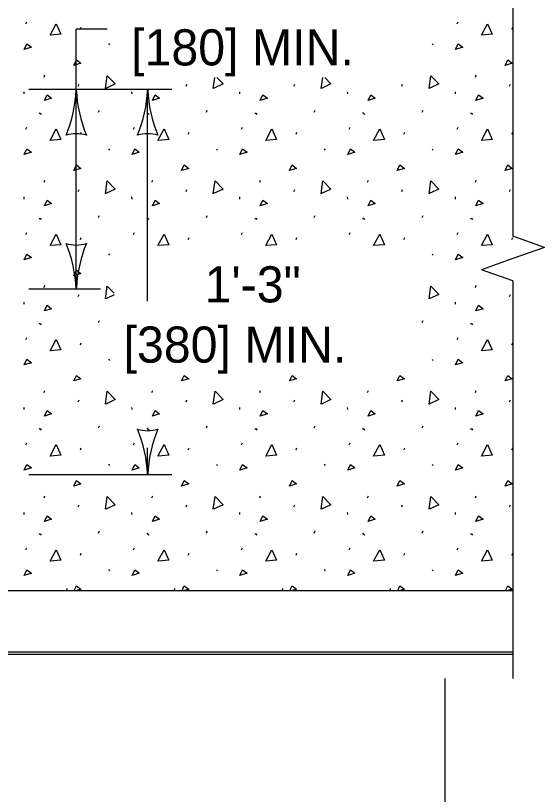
# Model space of a CAD drawing. Extents: x 49991.4 to 50021, y 49987.6 to 50011.4.
# Drawn here: x 50011.209 to 50012.088, y 49995.271 to 49996.564 of the extents above; entities that cross this region are included whole.
import ezdxf

# ---------------------------------------------------------------- set-up
doc = ezdxf.new("R2010")
doc.units = 0
for name, color, linetype in [('Level 1', 7, 'Continuous'), ('Level 2', 7, 'Continuous'), ('Level 3', 7, 'Continuous'), ('Level 6', 7, 'Continuous')]:
    doc.layers.add(name, color=color, linetype=linetype)

msp = doc.modelspace()

# ---------------------------------------------------------------- linework, layer by layer
at = {"layer": 'Level 1'}
for p, q in [((50011.2259, 49996.5503), (50011.2274, 49996.5536)), ((50011.3167, 49996.5417), (50011.3182, 49996.545)), ((50011.9425, 49996.5503), (50011.944, 49996.5536)), ((50012.0333, 49996.5417), (50012.0348, 49996.545)), ((50011.2233, 49996.5081), (50011.2278, 49996.5174)), ((50011.2352, 49996.5118), (50011.2233, 49996.5081)), ((50011.2278, 49996.5174), (50011.2352, 49996.5118)), ((50011.3633, 49996.5178), (50011.3648, 49996.5156)), ((50011.9008, 49996.5178), (50011.9023, 49996.5156)), ((50011.9399, 49996.5081), (50011.9444, 49996.5174)), ((50011.9519, 49996.5118), (50011.9399, 49996.5081)), ((50011.9444, 49996.5174), (50011.9519, 49996.5118)), ((50011.2563, 49996.4622), (50011.2577, 49996.4656)), ((50011.5375, 49996.4431), (50011.54, 49996.4614)), ((50011.7166, 49996.4431), (50011.7192, 49996.4614)), ((50011.9729, 49996.4622), (50011.9744, 49996.4656)), ((50011.3129, 49996.4469), (50011.3144, 49996.4503)), ((50011.4921, 49996.4469), (50011.4936, 49996.4503)), ((50011.6713, 49996.4469), (50011.6728, 49996.4503)), ((50011.8504, 49996.4469), (50011.8519, 49996.4503)), ((50012.0296, 49996.4469), (50012.0311, 49996.4503)), ((50011.2225, 49996.4376), (50011.2228, 49996.4342)), ((50011.4016, 49996.4376), (50011.402, 49996.4342)), ((50011.5808, 49996.4376), (50011.5812, 49996.4342)), ((50011.7599, 49996.4376), (50011.7603, 49996.4342)), ((50011.9391, 49996.4376), (50011.9395, 49996.4342)), ((50011.2479, 49996.4032), (50011.2494, 49996.4009)), ((50011.3469, 49996.4037), (50011.3484, 49996.407)), ((50011.4271, 49996.4032), (50011.4286, 49996.4009)), ((50011.526, 49996.4037), (50011.5275, 49996.407)), ((50011.6062, 49996.4032), (50011.6077, 49996.4009)), ((50011.7052, 49996.4037), (50011.7067, 49996.407)), ((50011.7854, 49996.4032), (50011.7869, 49996.4009)), ((50011.8844, 49996.4037), (50011.8859, 49996.407)), ((50011.9646, 49996.4032), (50011.966, 49996.4009)), ((50011.2499, 49996.4023), (50011.2514, 49996.4001)), ((50011.4291, 49996.4023), (50011.4306, 49996.4001)), ((50011.6082, 49996.4023), (50011.6097, 49996.4001)), ((50011.7874, 49996.4023), (50011.7889, 49996.4001)), ((50011.9665, 49996.4023), (50011.968, 49996.4001)), ((50011.2259, 49996.3755), (50011.2274, 49996.3789)), ((50011.4051, 49996.3755), (50011.4066, 49996.3789)), ((50011.5842, 49996.3755), (50011.5857, 49996.3789)), ((50011.7634, 49996.3755), (50011.7649, 49996.3789)), ((50011.9425, 49996.3755), (50011.944, 49996.3789)), ((50011.3167, 49996.367), (50011.3182, 49996.3703)), ((50011.4958, 49996.367), (50011.4973, 49996.3703)), ((50011.675, 49996.367), (50011.6765, 49996.3703)), ((50011.8541, 49996.367), (50011.8556, 49996.3703)), ((50012.0333, 49996.367), (50012.0348, 49996.3703)), ((50011.2233, 49996.3334), (50011.2278, 49996.3427)), ((50011.2278, 49996.3427), (50011.2352, 49996.3371)), ((50011.3633, 49996.3431), (50011.3648, 49996.3409)), ((50011.4025, 49996.3334), (50011.4069, 49996.3427)), ((50011.4069, 49996.3427), (50011.4144, 49996.3371)), ((50011.5425, 49996.3431), (50011.5439, 49996.3409)), ((50011.5816, 49996.3334), (50011.5861, 49996.3427)), ((50011.5861, 49996.3427), (50011.5936, 49996.3371)), ((50011.7216, 49996.3431), (50011.7231, 49996.3409)), ((50011.7608, 49996.3334), (50011.7653, 49996.3427)), ((50011.7653, 49996.3427), (50011.7727, 49996.3371)), ((50011.9008, 49996.3431), (50011.9023, 49996.3409)), ((50011.9399, 49996.3334), (50011.9444, 49996.3427)), ((50011.9444, 49996.3427), (50011.9519, 49996.3371)), ((50011.2352, 49996.3371), (50011.2233, 49996.3334)), ((50011.4144, 49996.3371), (50011.4025, 49996.3334)), ((50011.5936, 49996.3371), (50011.5816, 49996.3334)), ((50011.7727, 49996.3371), (50011.7608, 49996.3334)), ((50011.9519, 49996.3371), (50011.9399, 49996.3334)), ((50011.2563, 49996.2875), (50011.2577, 49996.2909)), ((50011.4354, 49996.2875), (50011.4369, 49996.2909)), ((50011.6146, 49996.2875), (50011.6161, 49996.2909)), ((50011.7937, 49996.2875), (50011.7952, 49996.2909)), ((50011.9729, 49996.2875), (50011.9744, 49996.2909)), ((50011.3129, 49996.2722), (50011.3144, 49996.2756)), ((50011.4921, 49996.2722), (50011.4936, 49996.2756)), ((50011.6713, 49996.2722), (50011.6728, 49996.2756)), ((50011.8504, 49996.2722), (50011.8519, 49996.2756)), ((50012.0296, 49996.2722), (50012.0311, 49996.2756)), ((50011.2225, 49996.2629), (50011.2228, 49996.2595)), ((50011.4016, 49996.2629), (50011.402, 49996.2595)), ((50011.5808, 49996.2629), (50011.5812, 49996.2595)), ((50011.7599, 49996.2629), (50011.7603, 49996.2595)), ((50011.9391, 49996.2629), (50011.9395, 49996.2595)), ((50011.2479, 49996.2285), (50011.2494, 49996.2262)), ((50011.2499, 49996.2276), (50011.2514, 49996.2254)), ((50011.3469, 49996.229), (50011.3484, 49996.2323)), ((50011.4271, 49996.2285), (50011.4286, 49996.2262)), ((50011.4291, 49996.2276), (50011.4306, 49996.2254)), ((50011.526, 49996.229), (50011.5275, 49996.2323)), ((50011.6062, 49996.2285), (50011.6077, 49996.2262)), ((50011.6082, 49996.2276), (50011.6097, 49996.2254)), ((50011.7052, 49996.229), (50011.7067, 49996.2323)), ((50011.7854, 49996.2285), (50011.7869, 49996.2262)), ((50011.7874, 49996.2276), (50011.7889, 49996.2254)), ((50011.8844, 49996.229), (50011.8859, 49996.2323)), ((50011.9646, 49996.2285), (50011.966, 49996.2262)), ((50011.9665, 49996.2276), (50011.968, 49996.2254)), ((50011.2259, 49996.2008), (50011.2274, 49996.2042)), ((50011.3167, 49996.1922), (50011.3182, 49996.1956)), ((50011.4051, 49996.2008), (50011.4066, 49996.2042)), ((50011.4958, 49996.1922), (50011.4973, 49996.1956)), ((50011.5842, 49996.2008), (50011.5857, 49996.2042)), ((50011.675, 49996.1922), (50011.6765, 49996.1956)), ((50011.7634, 49996.2008), (50011.7649, 49996.2042)), ((50011.8541, 49996.1922), (50011.8556, 49996.1956)), ((50011.9425, 49996.2008), (50011.944, 49996.2042)), ((50012.0333, 49996.1922), (50012.0348, 49996.1956)), ((50011.2233, 49996.1587), (50011.2278, 49996.168)), ((50011.2352, 49996.1624), (50011.2233, 49996.1587)), ((50011.2278, 49996.168), (50011.2352, 49996.1624)), ((50011.3633, 49996.1684), (50011.3648, 49996.1661)), ((50011.9008, 49996.1684), (50011.9023, 49996.1661)), ((50011.9399, 49996.1587), (50011.9444, 49996.168)), ((50011.9519, 49996.1624), (50011.9399, 49996.1587)), ((50011.9444, 49996.168), (50011.9519, 49996.1624)), ((50011.2563, 49996.1128), (50011.2577, 49996.1162)), ((50011.9729, 49996.1128), (50011.9744, 49996.1162)), ((50011.3129, 49996.0975), (50011.3144, 49996.1009)), ((50011.3725, 49996.1002), (50011.3587, 49996.0938)), ((50012.0296, 49996.0975), (50012.0311, 49996.1009)), ((50011.2225, 49996.0881), (50011.2228, 49996.0848)), ((50011.9391, 49996.0881), (50011.9395, 49996.0848)), ((50011.2479, 49996.0537), (50011.2494, 49996.0515)), ((50011.3469, 49996.0542), (50011.3484, 49996.0576)), ((50011.8844, 49996.0542), (50011.8859, 49996.0576)), ((50011.9646, 49996.0537), (50011.966, 49996.0515)), ((50011.2499, 49996.0529), (50011.2514, 49996.0507)), ((50011.9665, 49996.0529), (50011.968, 49996.0507)), ((50011.2259, 49996.0261), (50011.2274, 49996.0295)), ((50011.9425, 49996.0261), (50011.944, 49996.0295)), ((50011.3167, 49996.0175), (50011.3182, 49996.0209)), ((50012.0333, 49996.0175), (50012.0348, 49996.0209)), ((50011.2233, 49995.9839), (50011.2278, 49995.9933)), ((50011.2278, 49995.9933), (50011.2352, 49995.9877)), ((50011.3633, 49995.9936), (50011.3648, 49995.9914)), ((50011.9008, 49995.9936), (50011.9023, 49995.9914)), ((50011.9399, 49995.9839), (50011.9444, 49995.9933)), ((50011.9444, 49995.9933), (50011.9519, 49995.9877)), ((50011.2352, 49995.9877), (50011.2233, 49995.9839)), ((50011.9519, 49995.9877), (50011.9399, 49995.9839)), ((50011.2563, 49995.9381), (50011.2577, 49995.9414)), ((50011.4354, 49995.9381), (50011.4369, 49995.9414)), ((50011.6146, 49995.9381), (50011.6161, 49995.9414)), ((50011.7937, 49995.9381), (50011.7952, 49995.9414)), ((50011.9729, 49995.9381), (50011.9744, 49995.9414)), ((50011.3129, 49995.9228), (50011.3144, 49995.9261)), ((50011.4921, 49995.9228), (50011.4936, 49995.9261)), ((50011.6713, 49995.9228), (50011.6728, 49995.9261)), ((50011.8504, 49995.9228), (50011.8519, 49995.9261)), ((50012.0296, 49995.9228), (50012.0311, 49995.9261)), ((50011.2225, 49995.9134), (50011.2228, 49995.9101)), ((50011.4016, 49995.9134), (50011.402, 49995.9101)), ((50011.5808, 49995.9134), (50011.5812, 49995.9101)), ((50011.7599, 49995.9134), (50011.7603, 49995.9101)), ((50011.9391, 49995.9134), (50011.9395, 49995.9101)), ((50011.2479, 49995.879), (50011.2494, 49995.8768)), ((50011.2499, 49995.8782), (50011.2514, 49995.8759)), ((50011.3469, 49995.8795), (50011.3484, 49995.8829)), ((50011.4271, 49995.879), (50011.4286, 49995.8768)), ((50011.4291, 49995.8782), (50011.4306, 49995.8759)), ((50011.526, 49995.8795), (50011.5275, 49995.8829)), ((50011.6062, 49995.879), (50011.6077, 49995.8768)), ((50011.6082, 49995.8782), (50011.6097, 49995.8759)), ((50011.7052, 49995.8795), (50011.7067, 49995.8829)), ((50011.7854, 49995.879), (50011.7869, 49995.8768)), ((50011.7874, 49995.8782), (50011.7889, 49995.8759)), ((50011.8844, 49995.8795), (50011.8859, 49995.8829)), ((50011.9646, 49995.879), (50011.966, 49995.8768)), ((50011.9665, 49995.8782), (50011.968, 49995.8759)), ((50011.2259, 49995.8514), (50011.2274, 49995.8547)), ((50011.3167, 49995.8428), (50011.3182, 49995.8462)), ((50011.4051, 49995.8514), (50011.4066, 49995.8547)), ((50011.4958, 49995.8428), (50011.4973, 49995.8462)), ((50011.5842, 49995.8514), (50011.5857, 49995.8547)), ((50011.675, 49995.8428), (50011.6765, 49995.8462)), ((50011.7634, 49995.8514), (50011.7649, 49995.8547)), ((50011.8541, 49995.8428), (50011.8556, 49995.8462)), ((50011.9425, 49995.8514), (50011.944, 49995.8547)), ((50012.0333, 49995.8428), (50012.0348, 49995.8462)), ((50011.2233, 49995.8092), (50011.2278, 49995.8186)), ((50011.2352, 49995.813), (50011.2233, 49995.8092)), ((50011.2278, 49995.8186), (50011.2352, 49995.813)), ((50011.3633, 49995.8189), (50011.3648, 49995.8167)), ((50011.4025, 49995.8092), (50011.4069, 49995.8186)), ((50011.4144, 49995.813), (50011.4025, 49995.8092)), ((50011.4069, 49995.8186), (50011.4144, 49995.813)), ((50011.5425, 49995.8189), (50011.5439, 49995.8167)), ((50011.5816, 49995.8092), (50011.5861, 49995.8186)), ((50011.5936, 49995.813), (50011.5816, 49995.8092)), ((50011.5861, 49995.8186), (50011.5936, 49995.813)), ((50011.7216, 49995.8189), (50011.7231, 49995.8167)), ((50011.7608, 49995.8092), (50011.7653, 49995.8186)), ((50011.7727, 49995.813), (50011.7608, 49995.8092)), ((50011.7653, 49995.8186), (50011.7727, 49995.813)), ((50011.9008, 49995.8189), (50011.9023, 49995.8167)), ((50011.9399, 49995.8092), (50011.9444, 49995.8186)), ((50011.9519, 49995.813), (50011.9399, 49995.8092)), ((50011.9444, 49995.8186), (50011.9519, 49995.813)), ((50011.2563, 49995.7634), (50011.2577, 49995.7667)), ((50011.4354, 49995.7634), (50011.4369, 49995.7667)), ((50011.6146, 49995.7634), (50011.6161, 49995.7667)), ((50011.7937, 49995.7634), (50011.7952, 49995.7667)), ((50011.9729, 49995.7634), (50011.9744, 49995.7667)), ((50011.3129, 49995.7481), (50011.3144, 49995.7514)), ((50011.4921, 49995.7481), (50011.4936, 49995.7514)), ((50011.6713, 49995.7481), (50011.6728, 49995.7514)), ((50011.8504, 49995.7481), (50011.8519, 49995.7514)), ((50012.0296, 49995.7481), (50012.0311, 49995.7514)), ((50011.2225, 49995.7387), (50011.2228, 49995.7353)), ((50011.4016, 49995.7387), (50011.402, 49995.7353)), ((50011.5808, 49995.7387), (50011.5812, 49995.7353)), ((50011.7599, 49995.7387), (50011.7603, 49995.7353)), ((50011.9391, 49995.7387), (50011.9395, 49995.7353)), ((50011.2479, 49995.7043), (50011.2494, 49995.7021)), ((50011.3469, 49995.7048), (50011.3484, 49995.7082)), ((50011.4271, 49995.7043), (50011.4286, 49995.7021)), ((50011.526, 49995.7048), (50011.5275, 49995.7082)), ((50011.6062, 49995.7043), (50011.6077, 49995.7021)), ((50011.7052, 49995.7048), (50011.7067, 49995.7082)), ((50011.7854, 49995.7043), (50011.7869, 49995.7021)), ((50011.8844, 49995.7048), (50011.8859, 49995.7082)), ((50011.9646, 49995.7043), (50011.966, 49995.7021)), ((50011.2499, 49995.7034), (50011.2514, 49995.7012)), ((50011.4291, 49995.7034), (50011.4306, 49995.7012)), ((50011.6082, 49995.7034), (50011.6097, 49995.7012)), ((50011.7874, 49995.7034), (50011.7889, 49995.7012)), ((50011.9665, 49995.7034), (50011.968, 49995.7012)), ((50011.2259, 49995.6767), (50011.2274, 49995.68)), ((50011.4051, 49995.6767), (50011.4066, 49995.68)), ((50011.5842, 49995.6767), (50011.5857, 49995.68)), ((50011.7634, 49995.6767), (50011.7649, 49995.68)), ((50011.9425, 49995.6767), (50011.944, 49995.68)), ((50011.3167, 49995.6681), (50011.3182, 49995.6714)), ((50011.4958, 49995.6681), (50011.4973, 49995.6714)), ((50011.675, 49995.6681), (50011.6765, 49995.6714)), ((50011.8541, 49995.6681), (50011.8556, 49995.6714)), ((50012.0333, 49995.6681), (50012.0348, 49995.6714)), ((50011.2233, 49995.6345), (50011.2278, 49995.6438)), ((50011.2278, 49995.6438), (50011.2352, 49995.6382)), ((50011.3633, 49995.6442), (50011.3648, 49995.642)), ((50011.4025, 49995.6345), (50011.4069, 49995.6438)), ((50011.4069, 49995.6438), (50011.4144, 49995.6382)), ((50011.5425, 49995.6442), (50011.5439, 49995.642)), ((50011.5816, 49995.6345), (50011.5861, 49995.6438)), ((50011.5861, 49995.6438), (50011.5936, 49995.6382)), ((50011.7216, 49995.6442), (50011.7231, 49995.642)), ((50011.7608, 49995.6345), (50011.7653, 49995.6438)), ((50011.7653, 49995.6438), (50011.7727, 49995.6382)), ((50011.9008, 49995.6442), (50011.9023, 49995.642)), ((50011.9399, 49995.6345), (50011.9444, 49995.6438)), ((50011.9444, 49995.6438), (50011.9519, 49995.6382)), ((50011.2352, 49995.6382), (50011.2233, 49995.6345)), ((50011.4144, 49995.6382), (50011.4025, 49995.6345)), ((50011.5936, 49995.6382), (50011.5816, 49995.6345)), ((50011.7727, 49995.6382), (50011.7608, 49995.6345)), ((50011.9519, 49995.6382), (50011.9399, 49995.6345)), ((50011.2936, 49995.61), (50011.295, 49995.6134)), ((50011.4727, 49995.61), (50011.4742, 49995.6134)), ((50011.6519, 49995.61), (50011.6534, 49995.6134)), ((50011.831, 49995.61), (50011.8325, 49995.6134)), ((50009.9073, 49995.6094), (50011.8351, 49995.6094)), ((50011.8351, 49995.6094), (50012.0351, 49995.6094)), ((50009.7073, 49995.5073), (50012.0351, 49995.5073)), ((50009.7073, 49995.5034), (50012.0351, 49995.5034))]:
    msp.add_line(p, q, dxfattribs=at)
for points in [[(50011.2663, 49996.5316), (50011.2764, 49996.5506), (50011.2842, 49996.5331), (50011.2667, 49996.5316)], [(50011.983, 49996.5316), (50011.993, 49996.5506), (50012.0009, 49996.5331), (50011.9833, 49996.5316)], [(50011.3056, 49996.4815), (50011.31, 49996.4908), (50011.3175, 49996.4852), (50011.3056, 49996.4815)], [(50012.0222, 49996.4815), (50012.0267, 49996.4908), (50012.0341, 49996.4852), (50012.0222, 49996.4815)], [(50011.3583, 49996.4431), (50011.3613, 49996.4644), (50011.3746, 49996.4506), (50011.3587, 49996.4432)], [(50011.5433, 49996.4614), (50011.5538, 49996.4506), (50011.5378, 49996.4432)], [(50011.7225, 49996.4614), (50011.7329, 49996.4506), (50011.717, 49996.4432)], [(50011.8958, 49996.4431), (50011.8988, 49996.4644), (50011.9121, 49996.4506), (50011.8961, 49996.4432)], [(50011.257, 49996.4231), (50011.2615, 49996.4324), (50011.2689, 49996.4268), (50011.257, 49996.4231)], [(50011.4362, 49996.4231), (50011.4406, 49996.4324), (50011.4481, 49996.4268), (50011.4362, 49996.4231)], [(50011.6153, 49996.4231), (50011.6198, 49996.4324), (50011.6273, 49996.4268), (50011.6153, 49996.4231)], [(50011.7945, 49996.4231), (50011.799, 49996.4324), (50011.8064, 49996.4268), (50011.7945, 49996.4231)], [(50011.9736, 49996.4231), (50011.9781, 49996.4324), (50011.9856, 49996.4268), (50011.9736, 49996.4231)], [(50011.2663, 49996.3569), (50011.2764, 49996.3759), (50011.2842, 49996.3584), (50011.2667, 49996.3569)], [(50011.4455, 49996.3569), (50011.4556, 49996.3759), (50011.4634, 49996.3584), (50011.4459, 49996.3569)], [(50011.6246, 49996.3569), (50011.6347, 49996.3759), (50011.6425, 49996.3584), (50011.625, 49996.3569)], [(50011.8038, 49996.3569), (50011.8139, 49996.3759), (50011.8217, 49996.3584), (50011.8042, 49996.3569)], [(50011.983, 49996.3569), (50011.993, 49996.3759), (50012.0009, 49996.3584), (50011.9833, 49996.3569)], [(50011.3056, 49996.3067), (50011.31, 49996.3161), (50011.3175, 49996.3105), (50011.3056, 49996.3067)], [(50011.4847, 49996.3067), (50011.4892, 49996.3161), (50011.4967, 49996.3105), (50011.4847, 49996.3067)], [(50011.6639, 49996.3067), (50011.6684, 49996.3161), (50011.6758, 49996.3105), (50011.6639, 49996.3067)], [(50011.843, 49996.3067), (50011.8475, 49996.3161), (50011.855, 49996.3105), (50011.843, 49996.3067)], [(50012.0222, 49996.3067), (50012.0267, 49996.3161), (50012.0341, 49996.3105), (50012.0222, 49996.3067)], [(50011.3583, 49996.2684), (50011.3613, 49996.2897), (50011.3746, 49996.2759), (50011.3587, 49996.2685)], [(50011.5375, 49996.2684), (50011.5404, 49996.2897), (50011.5538, 49996.2759), (50011.5378, 49996.2685)], [(50011.7166, 49996.2684), (50011.7196, 49996.2897), (50011.7329, 49996.2759), (50011.717, 49996.2685)], [(50011.8958, 49996.2684), (50011.8988, 49996.2897), (50011.9121, 49996.2759), (50011.8961, 49996.2685)], [(50011.257, 49996.2484), (50011.2615, 49996.2577), (50011.2689, 49996.2521), (50011.257, 49996.2484)], [(50011.4362, 49996.2484), (50011.4406, 49996.2577), (50011.4481, 49996.2521), (50011.4362, 49996.2484)], [(50011.6153, 49996.2484), (50011.6198, 49996.2577), (50011.6273, 49996.2521), (50011.6153, 49996.2484)], [(50011.7945, 49996.2484), (50011.799, 49996.2577), (50011.8064, 49996.2521), (50011.7945, 49996.2484)], [(50011.9736, 49996.2484), (50011.9781, 49996.2577), (50011.9856, 49996.2521), (50011.9736, 49996.2484)], [(50011.2663, 49996.1822), (50011.2764, 49996.2012), (50011.2842, 49996.1837), (50011.2667, 49996.1822)], [(50011.4455, 49996.1822), (50011.4556, 49996.2012), (50011.4634, 49996.1837), (50011.4459, 49996.1822)], [(50011.6246, 49996.1822), (50011.6347, 49996.2012), (50011.6425, 49996.1837), (50011.625, 49996.1822)], [(50011.8038, 49996.1822), (50011.8139, 49996.2012), (50011.8217, 49996.1837), (50011.8042, 49996.1822)], [(50011.983, 49996.1822), (50011.993, 49996.2012), (50012.0009, 49996.1837), (50011.9833, 49996.1822)], [(50011.3056, 49996.132), (50011.31, 49996.1413), (50011.3175, 49996.1357), (50011.3056, 49996.132)], [(50011.3583, 49996.0936), (50011.3613, 49996.115), (50011.3725, 49996.1034)], [(50011.8958, 49996.0936), (50011.8988, 49996.115), (50011.9121, 49996.1012), (50011.8961, 49996.0938)], [(50011.257, 49996.0736), (50011.2615, 49996.083), (50011.2689, 49996.0774), (50011.257, 49996.0736)], [(50011.9736, 49996.0736), (50011.9781, 49996.083), (50011.9856, 49996.0774), (50011.9736, 49996.0736)], [(50011.2663, 49996.0074), (50011.2764, 49996.0265), (50011.2842, 49996.0089), (50011.2667, 49996.0074)], [(50011.983, 49996.0074), (50011.993, 49996.0265), (50012.0009, 49996.0089), (50011.9833, 49996.0074)], [(50011.3056, 49995.9573), (50011.31, 49995.9666), (50011.3175, 49995.961), (50011.3056, 49995.9573)], [(50011.4847, 49995.9573), (50011.4892, 49995.9666), (50011.4967, 49995.961), (50011.4847, 49995.9573)], [(50011.6639, 49995.9573), (50011.6684, 49995.9666), (50011.6758, 49995.961), (50011.6639, 49995.9573)], [(50011.843, 49995.9573), (50011.8475, 49995.9666), (50011.855, 49995.961), (50011.843, 49995.9573)], [(50012.0222, 49995.9573), (50012.0267, 49995.9666), (50012.0341, 49995.961), (50012.0222, 49995.9573)], [(50011.3583, 49995.9189), (50011.3613, 49995.9402), (50011.3746, 49995.9264), (50011.3587, 49995.919)], [(50011.5375, 49995.9189), (50011.5404, 49995.9402), (50011.5538, 49995.9264), (50011.5378, 49995.919)], [(50011.7166, 49995.9189), (50011.7196, 49995.9402), (50011.7329, 49995.9264), (50011.717, 49995.919)], [(50011.8958, 49995.9189), (50011.8988, 49995.9402), (50011.9121, 49995.9264), (50011.8961, 49995.919)], [(50011.257, 49995.8989), (50011.2615, 49995.9082), (50011.2689, 49995.9026), (50011.257, 49995.8989)], [(50011.4362, 49995.8989), (50011.4406, 49995.9082), (50011.4481, 49995.9026), (50011.4362, 49995.8989)], [(50011.6153, 49995.8989), (50011.6198, 49995.9082), (50011.6273, 49995.9026), (50011.6153, 49995.8989)], [(50011.7945, 49995.8989), (50011.799, 49995.9082), (50011.8064, 49995.9026), (50011.7945, 49995.8989)], [(50011.9736, 49995.8989), (50011.9781, 49995.9082), (50011.9856, 49995.9026), (50011.9736, 49995.8989)], [(50011.2663, 49995.8327), (50011.2764, 49995.8517), (50011.2842, 49995.8342), (50011.2667, 49995.8327)], [(50011.4455, 49995.8327), (50011.4556, 49995.8517), (50011.4634, 49995.8342), (50011.4459, 49995.8327)], [(50011.6246, 49995.8327), (50011.6347, 49995.8517), (50011.6425, 49995.8342), (50011.625, 49995.8327)], [(50011.8038, 49995.8327), (50011.8139, 49995.8517), (50011.8217, 49995.8342), (50011.8042, 49995.8327)], [(50011.983, 49995.8327), (50011.993, 49995.8517), (50012.0009, 49995.8342), (50011.9833, 49995.8327)], [(50011.3056, 49995.7826), (50011.31, 49995.7919), (50011.3175, 49995.7863), (50011.3056, 49995.7826)], [(50011.4847, 49995.7826), (50011.4892, 49995.7919), (50011.4967, 49995.7863), (50011.4847, 49995.7826)], [(50011.6639, 49995.7826), (50011.6684, 49995.7919), (50011.6758, 49995.7863), (50011.6639, 49995.7826)], [(50011.843, 49995.7826), (50011.8475, 49995.7919), (50011.855, 49995.7863), (50011.843, 49995.7826)], [(50012.0222, 49995.7826), (50012.0267, 49995.7919), (50012.0341, 49995.7863), (50012.0222, 49995.7826)], [(50011.3583, 49995.7442), (50011.3613, 49995.7655), (50011.3746, 49995.7517), (50011.3587, 49995.7443)], [(50011.5375, 49995.7442), (50011.5404, 49995.7655), (50011.5538, 49995.7517), (50011.5378, 49995.7443)], [(50011.7166, 49995.7442), (50011.7196, 49995.7655), (50011.7329, 49995.7517), (50011.717, 49995.7443)], [(50011.8958, 49995.7442), (50011.8988, 49995.7655), (50011.9121, 49995.7517), (50011.8961, 49995.7443)], [(50011.257, 49995.7242), (50011.2615, 49995.7335), (50011.2689, 49995.7279), (50011.257, 49995.7242)], [(50011.4362, 49995.7242), (50011.4406, 49995.7335), (50011.4481, 49995.7279), (50011.4362, 49995.7242)], [(50011.6153, 49995.7242), (50011.6198, 49995.7335), (50011.6273, 49995.7279), (50011.6153, 49995.7242)], [(50011.7945, 49995.7242), (50011.799, 49995.7335), (50011.8064, 49995.7279), (50011.7945, 49995.7242)], [(50011.9736, 49995.7242), (50011.9781, 49995.7335), (50011.9856, 49995.7279), (50011.9736, 49995.7242)], [(50011.2663, 49995.658), (50011.2764, 49995.677), (50011.2842, 49995.6595), (50011.2667, 49995.658)], [(50011.4455, 49995.658), (50011.4556, 49995.677), (50011.4634, 49995.6595), (50011.4459, 49995.658)], [(50011.6246, 49995.658), (50011.6347, 49995.677), (50011.6425, 49995.6595), (50011.625, 49995.658)], [(50011.8038, 49995.658), (50011.8139, 49995.677), (50011.8217, 49995.6595), (50011.8042, 49995.658)], [(50011.983, 49995.658), (50011.993, 49995.677), (50012.0009, 49995.6595), (50011.9833, 49995.658)], [(50011.3063, 49995.6094), (50011.31, 49995.6172), (50011.3175, 49995.6116), (50011.3106, 49995.6094)], [(50011.4855, 49995.6094), (50011.4892, 49995.6172), (50011.4967, 49995.6116), (50011.4897, 49995.6094)], [(50011.6646, 49995.6094), (50011.6684, 49995.6172), (50011.6758, 49995.6116), (50011.6689, 49995.6094)], [(50011.8438, 49995.6094), (50011.8475, 49995.6172), (50011.855, 49995.6116), (50011.8481, 49995.6094)], [(50012.0229, 49995.6094), (50012.0267, 49995.6172), (50012.0341, 49995.6116), (50012.0272, 49995.6094)]]:
    msp.add_lwpolyline(points, dxfattribs=at)
at = {"layer": 'Level 3'}
for p, q in [((50011.3098, 49996.4414), (50011.3098, 49996.5414)), ((50011.3609, 49996.5414), (50011.3098, 49996.5414)), ((50011.4684, 49996.4414), (50011.2312, 49996.4414)), ((50011.3098, 49996.1097), (50011.3098, 49996.4414)), ((50011.4284, 49996.0898), (50011.4284, 49996.4414)), ((50011.3498, 49996.1097), (50011.2312, 49996.1097)), ((50011.4284, 49995.8014), (50011.4284, 49995.8463)), ((50011.4685, 49995.8014), (50011.2312, 49995.8014)), ((50011.9225, 49995.1984), (50011.9225, 49995.4634))]:
    msp.add_line(p, q, dxfattribs=at)
for centre, radius, start, end in [((50011.0771, 49996.4529), 0.233, 337.9228, 357.1727), ((50011.532, 49996.4506), 0.2223, 182.3605, 202.544), ((50011.1957, 49996.4529), 0.233, 337.9228, 357.1727), ((50011.6506, 49996.4506), 0.2223, 182.3605, 202.544), ((50011.3098, 49996.3132), 0.0548, 72.1388, 107.8612), ((50011.4284, 49996.3132), 0.0548, 72.1388, 107.8612), ((50011.3098, 49996.2379), 0.0548, 252.1388, 287.8612), ((50011.0771, 49996.0982), 0.233, 2.8273, 22.0772), ((50011.532, 49996.1005), 0.2223, 157.456, 177.6395), ((50011.4284, 49995.9296), 0.0548, 252.1388, 287.8612), ((50011.1957, 49995.7899), 0.233, 2.8273, 22.0772), ((50011.6506, 49995.7923), 0.2223, 157.456, 177.6395)]:
    msp.add_arc(centre, radius, start, end, dxfattribs=at)
at = {"layer": 'Level 6'}
for p, q in [((50012.0351, 49997.1707), (50012.0351, 49996.3166)), ((50012.0351, 49996.3166), (50012.0351, 49996.1977)), ((50012.0875, 49996.1792), (50012.0351, 49996.1977)), ((50012.0875, 49996.1792), (50012.0351, 49996.1606)), ((50012.0351, 49996.1606), (50011.9828, 49996.1421)), ((50012.0351, 49996.1235), (50011.9828, 49996.1421)), ((50012.0351, 49996.1235), (50012.0351, 49996.0056)), ((50012.0351, 49996.0056), (50012.0351, 49995.4634))]:
    msp.add_line(p, q, dxfattribs=at)

# ---------------------------------------------------------------- texts
at = {"layer": 'Level 2'}
for s, p in [('[180] MIN.', (50011.4009, 49996.4814)), ('1\'-3" ', (50011.523, 49996.0878)), ('[380] MIN.', (50011.3883, 49995.9878))]:
    msp.add_text(s, height=0.06, dxfattribs=at).set_placement(p)

doc.saveas('drawing.dxf')
